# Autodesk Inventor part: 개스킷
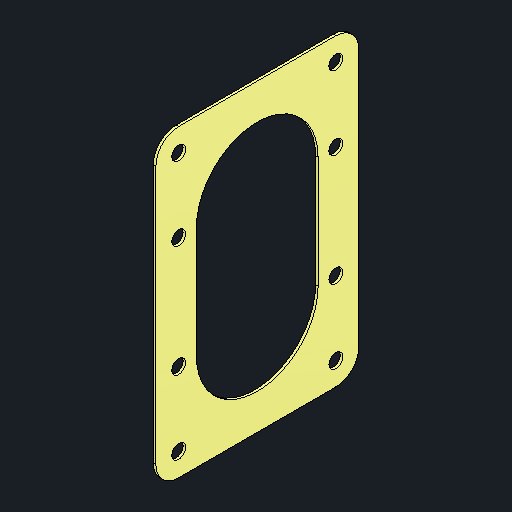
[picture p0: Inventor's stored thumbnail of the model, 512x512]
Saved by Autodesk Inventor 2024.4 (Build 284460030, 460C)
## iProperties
Created: 2026-09
Part Number: 개스킷
Material: 스테인리스스틸
Document SubType Name: Modeling
Designer: user
Density: 8 g/cm^3
Appearance: 기본값
Author: jhkim
Sending System: Autodesk Inventor 2027
Preprocessor: ST-DEVELOPER v20.1
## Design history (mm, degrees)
feature "솔리드1"
node "솔리드2"
